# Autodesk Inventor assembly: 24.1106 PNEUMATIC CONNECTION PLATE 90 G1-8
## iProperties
Created: 2007-06
Part Number: 24.1106 PNEUMATIC CONNECTION PLATE 90 G1-8
Document SubType Name: Assembly
Designer: Andy Moles
Author: Andy Moles
